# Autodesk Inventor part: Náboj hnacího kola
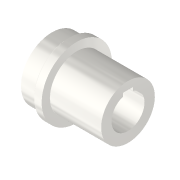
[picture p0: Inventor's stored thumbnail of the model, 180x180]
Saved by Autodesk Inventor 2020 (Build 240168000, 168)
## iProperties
Created: 2025-03
Part Number: Náboj hnacího kola
Material: Ocel
Document SubType Name: Modeling
Designer: doma
Density: 7.85 g/cm^3
Appearance: Ocel
Mass: 1732.38 g
Surface Area: 414.738 cm^2
Volume: 220.685 cm^3
Author: doma
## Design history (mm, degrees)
sketch "Náčrt1"
  geometry: L1 (-46, 0)-(46, 0); L2 (-16, 42.5)-(-26, 42.5); L3 (-26, 42.5)-(-26, 37.5); L4 (-26, 37.5)-(-46, 37.5); L5 (-46, 37.5)-(-46, 27.5); L6 (-16, 42.5)-(-16, 32.5); L7 (-16, 32.5)-(46, 32.5); L8 (46, 32.5)-(46, 20); L9 (-46, 27.5)-(-36, 27.5); L10 (-36, 20)-(46, 20); L11 (-36, 27.5)-(-36, 20); 2 further points
  constraints: 22 end point, 5 perpendicular, 3 horizontal, 2 point on line, 2 vertical, 1 coincident, 1 midpoint
  dimensions: "d1" = 42.5 distance between parallel lines of L1 L2; "d2" = 37.5 distance between parallel lines of L1 L4; "d4" = 20 distance of L3.end L4.end; "d5" = 32.5 distance between parallel lines of L1 L7; "d6" = 10 distance of L2.start L2.end; "d8" = 27.5 distance between parallel lines of L1 L9; "d10" = 20 distance between parallel lines of L1 L10; "d12" = 82 distance of L10.start L8.end; "d18" = 10 distance of L5.end L9.end
revolve "Rotace1" sketch "Náčrt1" stored, may be unused: angle "d13" = 90 deg
sketch "Náčrt2"
  geometry: L1 (6, 16.9)-(6, 23.1); L2 (6, 23.1)-(-6, 23.1); L3 (-6, 23.1)-(-6, 16.9); L4 (-6, 16.9)-(6, 16.9); L5 (6, 16.9)-(-6, 23.1); L6 (6, 23.1)-(-6, 16.9); 5 further points
  constraints: 12 end point, 2 midpoint, 2 parallel, 1 perpendicular, 1 vertical, 2 other
  dimensions: "d14" = 3.1 distance from line of L2 point (0, 20); "d15" = 12 distance of L1.end L2.end
extrude "Vysunutí1" cut sketch "Náčrt2" extent not by distance; stored distance "d16" = 0; taper "d17" = 0 deg
fillet "Zaoblení1" dims "d19" = 0.2
chamfer "Zkosení1" distance "d20" = 1; stored, may be unused: second distance "d21" = 2, angle "d22" = 45 deg
node "Těleso1"
